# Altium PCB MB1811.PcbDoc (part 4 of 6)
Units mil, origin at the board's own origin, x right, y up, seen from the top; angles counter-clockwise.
Board outline 3480.3 x 4291.34 mil, 4 copper layers (Top Layer, L2_VCC, L3_GND, Bottom Layer), stack 30.59 mil thick; 371 components, 285 nets, 1369 pads, 606 vias.
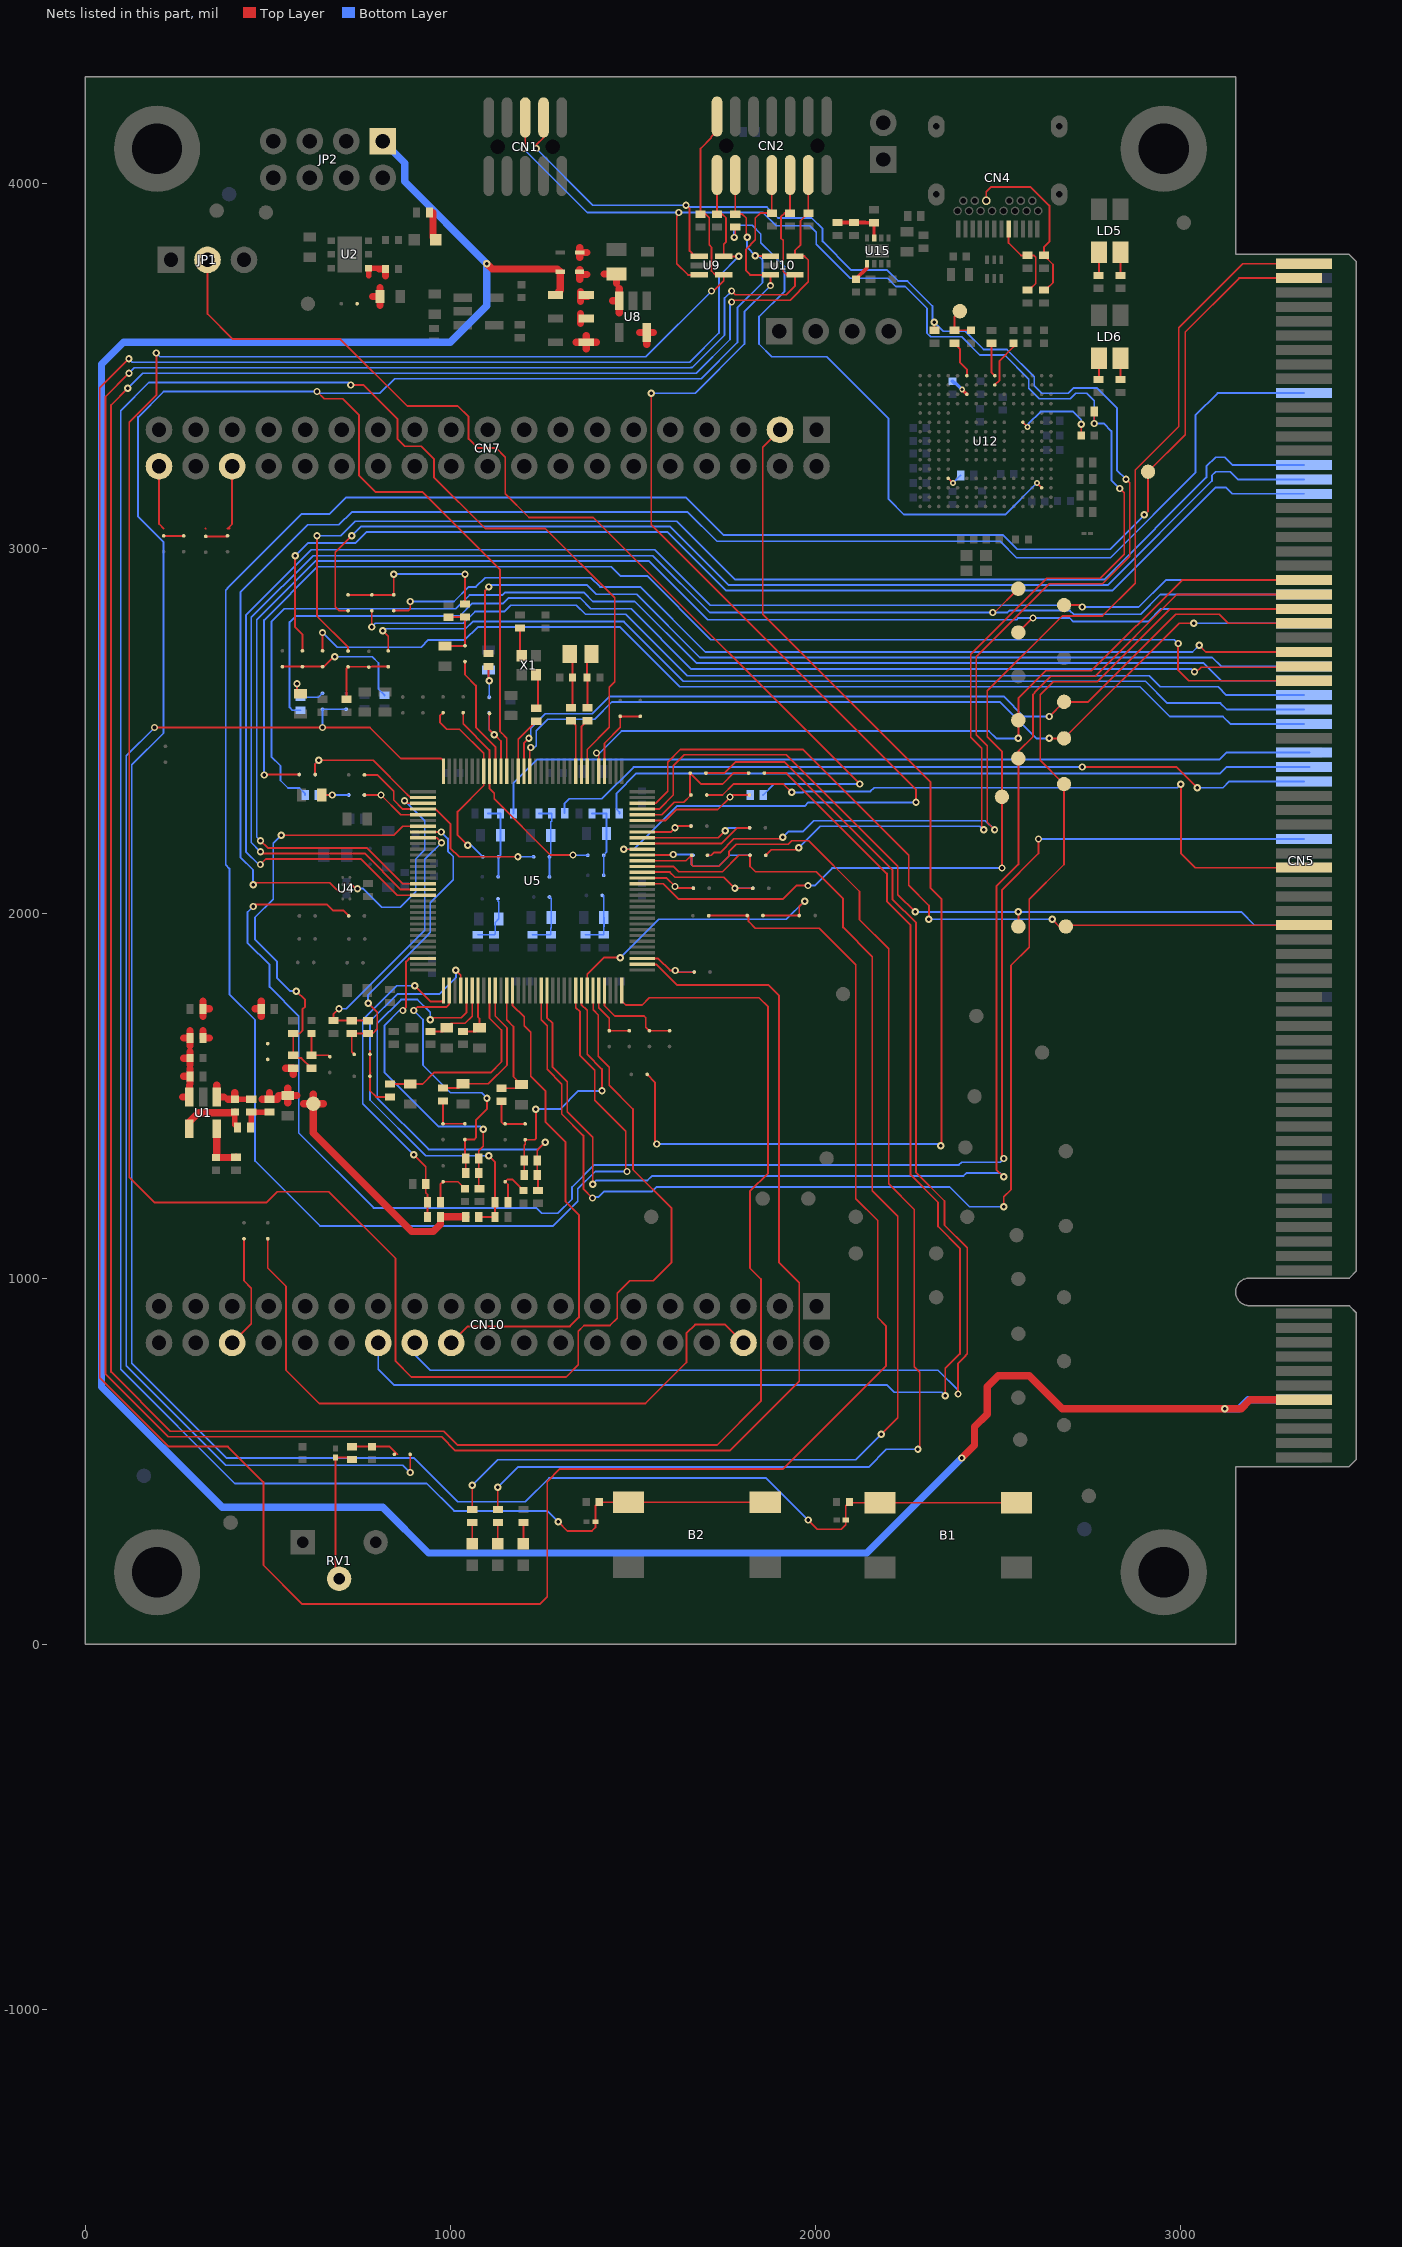
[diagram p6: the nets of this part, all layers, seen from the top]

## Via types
v1: diameter 20, hole 10, Top Layer to Bottom Layer, tented both sides, 524 vias
v2: diameter 16, hole 8, Top Layer to Bottom Layer, tented both sides, 82 vias

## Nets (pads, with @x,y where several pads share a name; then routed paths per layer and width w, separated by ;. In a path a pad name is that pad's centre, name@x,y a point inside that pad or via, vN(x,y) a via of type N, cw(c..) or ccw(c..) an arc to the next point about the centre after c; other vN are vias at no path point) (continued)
M2_PWM_WL: CN5.B40 SB48.2 | length 1871.8
  Top Layer w5: SB48.2@1702.11,2325 1744.99,2325 1775,2355.01 1912.06,2355.01 v1(1934.87,2332.2) ; v1(2999.99,2354.7) 2999.99,2165.01 3039.01,2125.99 CN5.B40@3336.8,2125.99
  Bottom Layer w5: v1(1934.87,2332.2) 1964.93,2332.2 1967.43,2334.7 2149.87,2334.7 2159.87,2344.7 2989.99,2344.7 v1(2999.99,2354.7)
M2_Res.Ex: CN5.B53 SB7.2 | length 3600
  Top Layer w5: v1(489.99,2379.7) 491.36,2381.07 SB7.2@586.37,2381.07 ; v1(2992.49,2739.7) 2992.49,2667.07 3021.76,2637.8 CN5.B53@3336.8,2637.81
  Bottom Layer w5: v1(489.99,2379.7) 489.99,2803.79 635.9,2949.7 1440.12,2949.7 1465.12,2924.7 1538.65,2924.7 1713.34,2750.01 2982.18,2750.01 v1(2992.49,2739.7)
M2_Resolver_Cos: C19.2 R20.2 R96.2 SB33.2 | length 179.4
  Top Layer w5: C19.2@984.99,2732.56 1038.91,2732.56 SB33.2@1039.99,2733.64 R20.2@1039.99,2812.3 995.19,2812.3 R96.2@994.87,2811.98
M2_Resolver_Cos_C: CN5.B55 SB27.1 | length 2639.9
  Top Layer w5: SB27.1@844.83,2830 884.87,2830 889.87,2835 v1(889.87,2854.7) ; v1(3049.87,2734.7) 3068.03,2716.54 CN5.B55@3336.8,2716.55
  Bottom Layer w5: v1(889.87,2854.7) 1009.87,2854.7 1049.87,2894.7 1069.87,2894.7 1094.87,2919.7 1384.87,2919.7 1409.87,2894.7 1519.87,2894.7 1698.03,2716.54 3031.71,2716.54 v1(3049.87,2734.7)
M2_Resolver_Sin: C24.2 R25.2 SB36.2 | length 137.8
  Top Layer w5: v1(579.87,2629.86) 579.87,2612.26 C24.2@589.87,2602.26
  Bottom Layer w5: v1(579.87,2629.86) 579.87,2602.42 R25.2@589.87,2592.42 638.97,2592.42 SB36.2@649.87,2603.32
M2_Resolver_Sin_C: CN5.B54 R25.1 | length 3161.4
  Top Layer w5: v1(3037.36,2662.19) 3042.38,2662.19 3055.2,2675.01 3334.63,2675.01 CN5.B54@3336.8,2677.18
  Bottom Layer w5: R25.1@589.87,2556.98 567.59,2556.98 559.87,2564.7 559.87,2798.47 576.1,2814.7 1024.87,2814.7 1059.87,2849.7 1144.87,2849.7 1159.87,2864.7 1354.87,2864.7 1384.87,2834.7 1494.87,2834.7 1659.87,2669.7 3029.85,2669.7 v1(3037.36,2662.19)
M2_SHUNT1+: SB17.1 SB78.2 U5.36 | length 608.6
  Top Layer w5: SB17.1@764.68,2380.01 799.55,2380.01 844.87,2334.69 844.87,2311.35 869.68,2286.54 U5.36@924.99,2286.55 959.33,2286.54 999.87,2246 999.87,2179.69 1023.81,2155.75 v1(1184.87,2155.75)
  Bottom Layer w5: v1(1184.87,2155.75) SB78.2@1227.91,2155.75
M2_SHUNT1+_C: CN5.A46 R65.1 | length 2123.2
  Top Layer w5: v1(2729.87,2401.58) 2988.42,2401.58 v1(3044.99,2345.01)
  Bottom Layer w5: R65.1@1312.71,2275.01 1312.7,2302.53 1324.87,2314.7 1414.88,2314.7 1501.76,2401.58 v1(2729.87,2401.58) ; v1(3044.99,2345.01) 3115.19,2345.01 3132.39,2362.21 CN5.A46@3336.8,2362.22
M2_SHUNT2+: SB34.1 SB74.2 U5.24 | length 591.4
  Top Layer w5: SB34.1@1034.99,2550.33 1034.99,2520.01 1106.88,2448.12 1106.88,2343.12 1119.99,2330.01 1119.99,2314.57 1273.87,2160.69 v1(1335.87,2160.69)
  Bottom Layer w5: v1(1335.87,2160.69) 1336.56,2160 SB74.2@1376.37,2160
M2_SHUNT2+_C: CN5.A47 R61.1 | length 1984.9
  Bottom Layer w5: R61.1@1462.6,2274.7 1462.59,2278.44 1454.87,2286.16 1454.87,2329.69 1509.26,2384.08 3107.24,2384.08 3124.74,2401.58 CN5.A47@3336.8,2401.59 CN5.A47@3351.8,2401.58
M2_SHUNT3+: SB30.1 SB79.2 U5.25 | length 531.6
  Top Layer w5: SB30.1@980,2550.32 971.15,2541.48 971.15,2523.85 989.99,2505.01 1024.99,2505.01 1091.13,2438.87 1091.13,2350.96 1019.87,2279.7 1019.87,2215.42 v1(1047.73,2187.56)
  Bottom Layer w5: v1(1047.73,2187.56) 1057.13,2187.56 SB79.2@1088.62,2156.07
M2_SHUNT3+_C: CN5.A48 R67.1 | length 2296.5
  Bottom Layer w5: R67.1@1172.59,2274.7 1172.59,2357.42 1237.68,2422.51 3106.3,2422.51 3124.74,2440.95 3336.8,2440.95 CN5.A48@3351.8,2440.95
M2_TEMP_ID: C5.2 R73.2 SB87.2 | length 116.1
  Top Layer w5: C5.2@647.55,2325.01 v1(676.84,2325.01) v1@679.99,2325.01
  Bottom Layer w5: R73.2@637.71,2325.01 v1(676.84,2325.01) SB87.2@721.37,2325.01
M2_TEMP_ID_C: CN5.A53 R73.1 | length 3491.7
  Bottom Layer w5: R73.1@602.28,2325.01 602.28,2328.75 586.93,2344.1 555.47,2344.1 534.87,2364.7 534.87,2404.7 509.87,2429.7 509.87,2799.69 544.88,2834.7 1014.87,2834.7 1052.37,2872.2 1142.37,2872.2 1149.87,2879.7 1364.87,2879.7 1389.87,2854.7 1504.87,2854.7 1673.03,2686.54 3061.13,2686.54 3109.87,2637.8 CN5.A53@3336.8,2637.81
M2_Timer_ETR: CN5.A42 SB16.2 | length 4708.8
  Top Layer w5: v1(459.87,2019.7) 465.18,2025.01 662.34,2025.01 678.37,2008.98 706.34,2008.98 SB16.2@721.37,1993.95 ; v1(2514.87,1329.7) 2509.99,1334.58 2509.99,2064.81 2609.99,2164.81 v1(2609.99,2204.73)
  Bottom Layer w5: v1(459.87,2019.7) 444.87,2004.7 444.87,1919.7 504.87,1859.7 504.87,1799.7 584.87,1719.7 584.87,1399.69 789.86,1194.7 1234.88,1194.7 1249.88,1179.7 1294.2,1179.7 1332.87,1218.37 1332.87,1251.67 1393.4,1312.2 2392.37,1312.2 2399.87,1319.7 2504.87,1319.7 v1(2514.87,1329.7) ; v1(2609.99,2204.73) CN5.A42@3336.8,2204.74
M2_VBUS: C4.2 R72.2 SB86.2 | length 114.3
  Top Layer w5: R72.2@1104.56,2676.86 1104.56,2639.41 v1(1106.24,2637.73)
  Bottom Layer w5: C4.2@1104.56,2667.02 1104.56,2639.41 v1(1106.24,2637.73) SB86.2@1106.24,2593.21
M2_VBUS_C: CN5.A54 R72.1 | length 2516.7
  Top Layer w5: R72.1@1104.56,2712.29 1094.87,2721.98 1094.87,2884.7 v1(1104.87,2894.7)
  Bottom Layer w5: v1(1104.87,2894.7) 1109.87,2899.7 1374.87,2899.7 1399.87,2874.7 1509.87,2874.7 1683.03,2701.54 3085.51,2701.54 3109.87,2677.18 CN5.A54@3336.8,2677.18
M2_VOL+_U_C: CN5.A50 SB10.1 | length 2886
  Top Layer w5: SB10.1@649.99,2719.69 v1(649.99,2769.7)
  Bottom Layer w5: v1(649.99,2769.7) 689.99,2729.7 919.87,2729.7 939.87,2749.7 1039.87,2749.7 1074.87,2784.7 1464.87,2784.7 1628.03,2621.54 2888.02,2621.54 2969.55,2540.01 3115,2540.01 3135.32,2519.69 CN5.A50@3336.8,2519.7
M2_VOL+_V_C: CN5.A51 SB25.1 | length 2693.3
  Top Layer w5: v1(814.99,2775.01) 829.99,2760.01 SB25.1@829.99,2719.69
  Bottom Layer w5: v1(814.99,2775.01) 819.99,2780.01 1041.4,2780.01 1061.09,2799.7 1474.88,2799.7 1638.04,2636.54 2903.02,2636.54 2963,2576.56 3108.19,2576.56 3125.69,2559.06 CN5.A51@3336.8,2559.07
M2_VOL+_W_C: CN5.A52 SB24.1 | length 2723.4
  Top Layer w5: v1(784.83,2785.01) SB24.1@784.83,2829.69
  Bottom Layer w5: v1(784.83,2785.01) 794.83,2795.01 1035.18,2795.01 1067.37,2827.2 1147.37,2827.2 1164.87,2844.7 1344.87,2844.7 1369.87,2819.7 1479.87,2819.7 1648.03,2651.54 2913.03,2651.54 2943.07,2621.5 3101.67,2621.5 3124.74,2598.43 CN5.A52@3336.8,2598.44
M3_Board_ID: CN5.A73 U4.3 | length 4405.8
  Top Layer w5: v1(459.87,2079.7) 465.18,2085.01 670.22,2085.01 682.22,2073.01 695.08,2060.17 U4.3@705.15,2060.17
  Bottom Layer w5: v1(459.87,2079.7) 459.87,2119.7 424.99,2154.58 424.99,2879.83 609.86,3064.7 694.87,3064.7 729.87,3099.7 1649.87,3099.7 1729.87,3019.7 2504.87,3019.7 2549.87,2974.7 2807.16,2974.7 3039.87,3207.41 3039.87,3364.69 3100.38,3425.2 CN5.A73@3336.8,3425.21
M3_Emergency(BKIN2): CN5.B57 TP36.1 U5.18 | length 2427.3
  Top Layer w5: U5.18@1201.37,2389.7 1201.37,2466.39 v1(1214.99,2480.01) ; v1(2639.77,2539.79) TP36.1@2679.99,2580.01 2746.21,2580.01 2985.85,2819.65 3105.35,2819.65 3129.72,2795.28 CN5.B57@3336.8,2795.29
  Bottom Layer w5: v1(1214.99,2480.01) 1219.99,2485.01 1219.99,2507.2 1260.3,2547.51 1388.67,2547.51 1436.18,2595.02 1448.64,2595.02 ; 1448.65,2595.01 2514.55,2595.01 2569.77,2539.79 v1(2639.77,2539.79)
M3_Emergency(BKIN): CN5.A57 TP35.1 U5.17 | length 2431.1
  Top Layer w5: U5.17@1217.12,2389.7 1217.11,2452.13 v1(1219.99,2455.01) ; v1(2639.87,2480.01) TP35.1@2679.99,2480.01 2995.26,2795.28 v1(3034.87,2795.28)
  Bottom Layer w5: v1(1219.99,2455.01) 1229.99,2455.01 1234.99,2460.01 1234.99,2500.98 1266.52,2532.51 1394.93,2532.51 1442.43,2580.01 2504.55,2580.01 2604.55,2480.01 v1(2639.87,2480.01) ; v1(3034.87,2795.28) CN5.A57@3336.8,2795.29
M3_Enable1: CN5.B81 TP42.1 U5.88 | length 6961.3
  Top Layer w5: U5.88@1343.1,1789.7 1343.1,1743.12 1354.99,1731.23 1354.99,1610.99 1394.99,1570.99 1394.99,1489.57 1480,1404.56 1480,1370.26 ; 1479.99,1370.25 1479.99,1299.58 1483.33,1296.24 v1(1483.33,1294.2) ; v1(2899.63,3091.93) 2900.37,3091.93 2909.99,3101.55 TP42.1@2909.99,3210.01 3011.67,3311.69 3011.67,3592.69 3159.14,3740.16 CN5.B81@3322.83,3740.17
  Bottom Layer w5: v1(1483.33,1294.2) 1396.62,1294.2 1348.87,1246.45 1348.87,1213.15 1281.13,1145.41 642.94,1145.41 464.99,1323.36 464.99,1709.79 394.87,1779.91 394.87,2123.48 384.87,2133.48 384.87,2885.92 389.87,2890.92 389.87,2892.09 592.48,3094.7 669.87,3094.7 714.87,3139.7 1644.86,3139.7 1747.93,3036.63 2513.12,3036.63 2552.15,2997.6 2806.04,2997.6 2899.63,3091.19 v1(2899.63,3091.93)
M3_Enable2: CN5.B82 TP18.1 U5.112 | length 3230.1
  Top Layer w5: U5.112@1524.99,2081.83 1583.19,2081.81 1597.49,2067.51 1597.49,2067.44 1607.74,2057.19 1607.81,2057.19 1624.99,2040.01 1909.99,2040.01 1947,2077.02 v1(1979.2,2077.02) ; v1(2509.99,2125.01) TP18.1@2509.99,2320.01 2509.99,2444.57 2469.99,2484.57 2469.99,2610.01 2674.99,2815.01 2784.99,2815.01 2874.99,2905.01 2874.99,3214.82 2994.07,3333.9 2994.07,3604.09 3169.51,3779.53 CN5.B82@3336.8,3779.54
  Bottom Layer w5: v1(1979.2,2077.02) 1997.2,2077.02 2045.19,2125.01 v1(2509.99,2125.01)
M3_PWM_UH: CN5.A58 TP27.1 U5.49 | length 4179.5
  Top Layer w5: v1(479.99,2200.01) 499.99,2180.01 771.21,2180.01 869.41,2081.81 U5.49@924.99,2081.83 ; TP27.1@2554.99,2770.01 2594.68,2809.7 v1(2594.87,2809.7)
  Bottom Layer w5: v1(479.99,2200.01) 469.99,2210.01 469.99,2805.01 630.2,2965.22 1544.34,2965.22 1704.55,2805.01 2550.3,2805.01 2554.99,2809.7 v1(2594.87,2809.7) 2695.05,2809.7 2705.05,2799.7 2909.87,2799.7 2944.83,2834.66 CN5.A58@3336.8,2834.66
M3_PWM_UL: CN5.B58 TP34.1 U5.82 | length 4104.2
  Top Layer w5: U5.82@1248.61,1789.7 1248.61,1710.05 1264.99,1693.67 1264.99,1573.67 1304.99,1533.67 1304.99,1451.69 1363.99,1392.69 1363.99,1246.58 v1(1388.87,1221.7) ; v1(2514.87,1197.51) 2514.87,1224.69 2534.87,1244.69 2534.87,1858.55 2584.87,1908.55 2584.87,2039.7 2679.99,2134.82 TP34.1@2679.99,2355.01 2614.99,2420.01 2614.99,2600.01 2649.99,2635.01 2771.21,2635.01 2970.85,2834.65 CN5.B58@3336.79,2834.65
  Bottom Layer w5: v1(1388.87,1221.7) 1391.87,1224.7 1406.08,1224.7 1421.08,1239.7 1552.06,1239.7 1564.56,1252.2 2366.46,1252.2 2421.15,1197.51 v1(2514.87,1197.51)
M3_PWM_VH: CN5.A59 TP28.1 U5.50 | length 4281.8
  Top Layer w5: v1(479.99,2170.01) 484.99,2165.01 764.99,2165.01 863.94,2066.06 U5.50@924.99,2066.08 ; v1(2484.87,2824.7) 2489.68,2824.7 TP28.1@2554.99,2890.01
  Bottom Layer w5: v1(479.99,2170.01) 454.99,2195.01 454.99,2811.23 623.98,2980.22 1554.34,2980.22 1709.86,2824.7 v1(2484.87,2824.7) 2524.87,2824.7 2529.87,2829.7 2696.27,2829.7 2706.27,2819.7 2889.68,2819.7 2944,2874.02 CN5.A59@3336.8,2874.03
M3_PWM_VL: CN5.B59 TP24.1 U5.83 | length 3949.6
  Top Layer w5: U5.83@1264.36,1789.7 1264.36,1715.52 1279.99,1699.89 1279.99,1579.89 1319.99,1539.89 1319.99,1457.91 1389.87,1388.03 v1(1389.87,1259.7) ; v1(2514.87,1279.7) 2494.99,1299.58 2494.99,2074.83 2554.99,2134.83 TP24.1@2554.99,2425.01 2554.99,2444.81 2594.99,2484.81 2594.99,2600.01 2599.99,2605.01 2599.99,2606.23 2643.77,2650.01 2764.99,2650.01 2989,2874.02 CN5.B59@3336.8,2874.03
  Bottom Layer w5: v1(1389.87,1259.7) 1399.87,1269.7 1539.62,1269.7 1552.12,1282.2 2404.81,1282.2 2412.31,1289.7 2504.87,1289.7 v1(2514.87,1279.7)
M3_PWM_WH: CN5.A60 TP38.1 U5.51 | length 4313.3
  Top Layer w5: v1(479.87,2134.7) 495.18,2150.01 754.99,2150.01 854.68,2050.32 U5.51@924.99,2050.33 ; TP38.1@2679.99,2845.01 2724.57,2845.01 v1(2729.87,2839.7)
  Bottom Layer w5: v1(479.87,2134.7) 475.3,2134.7 439.99,2170.01 439.99,2817.45 619.07,2996.53 1559.25,2996.53 1711.08,2844.7 2724.87,2844.7 v1(2729.87,2839.7) 2884.68,2839.7 2958.37,2913.39 CN5.A60@3336.8,2913.4
M3_PWM_WL: CN5.B60 TP25.1 U5.5 | length 2266.8
  Top Layer w5: v1(1399.99,2440.01) 1406.09,2433.91 U5.5@1406.09,2389.7 ; v1(2554.99,2480.01) TP25.1@2554.99,2530.01 2554.99,2590.01 2629.99,2665.01 2754.99,2665.01 3003.37,2913.39 CN5.B60@3336.8,2913.4
  Bottom Layer w5: v1(1399.99,2440.01) 1408.53,2440.01 1468.53,2500.01 2474.56,2500.01 2494.56,2480.01 v1(2554.99,2480.01)
M3_SHUNT1+_C: CN5.A66 SB9.1 | length 3247.7
  Top Layer w5: v1(574.87,2979.7) 574.87,2784.7 594.99,2764.58 SB9.1@594.99,2719.69
  Bottom Layer w5: v1(574.87,2979.7) 609.87,3014.7 739.87,3014.7 769.87,3044.7 1595.3,3044.7 1755.3,2884.7 2812.46,2884.7 3094.87,3167.11 3122.9,3167.11 3140.4,3149.61 CN5.A66@3336.8,3149.62
M3_SHUNT2+_C: CN5.A67 SB20.1 | length 3082
  Top Layer w5: SB20.1@719.83,2829.69 695.31,2829.69 684.99,2840.01 684.99,2989.82 v1(729.87,3034.7)
  Bottom Layer w5: v1(729.87,3034.7) 754.87,3059.7 1601.52,3059.7 1761.52,2899.7 2799.87,2899.7 3084.87,3184.7 3084.87,3199.69 3095.19,3210.01 3134.99,3210.01 3156.02,3188.98 CN5.A67@3336.8,3188.99
M3_SHUNT3+_C: CN5.A68 SB19.1 | length 3300.5
  Top Layer w5: v1(634.87,3034.7) 634.87,2814.69 719.83,2729.73 SB19.1@719.83,2719.37
  Bottom Layer w5: v1(634.87,3034.7) 699.87,3034.7 739.87,3074.7 1619.87,3074.7 1779.87,2914.7 2789.87,2914.7 3069.87,3194.7 3069.87,3224.71 3094.86,3249.7 3120.29,3249.7 3141.64,3228.35 CN5.A68@3336.8,3228.35
MCU.MCO: C33.2 R90.2 TP43.1 | length 103.5
  Top Layer w5: TP43.1@2394.87,3649.7 2379.87,3634.7 R90.2@2379.87,3597.42 C33.2@2424.87,3597.42
MCU.SWCLK: CN2.6 R44.2 U5.98 U10.4 | length 8662.5
  Top Layer w5: v1(119.99,3480.01) 55.99,3416.01 55.99,739.23 227.21,568.01 975.77,568.01 1013.77,530.01 1764.99,530.01 1954.99,720.01 1954.99,990.01 1899.99,1045.01 1899.99,1775.01 1869.99,1805.01 1619.99,1805.01 1563.66,1861.34 U5.98@1524.99,1861.34 ; v1(1769.87,3704.7) 1779.87,3694.7 1919.87,3694.7 1943.33,3718.16 U10.4@1943.33,3749.11 1920.45,3749.11 1911.31,3758.25 1911.31,3843.26 1904.87,3849.7 1904.87,3908.12 1914.87,3918.12 R44.2@1929.92,3918.12 1929.92,4022.3 CN2.6@1929.99,4022.37
  Bottom Layer w5: v1(119.99,3480.01) 134.68,3494.7 1658.17,3494.7 1658.48,3495.01 1661.41,3495.01 1750.48,3584.08 1750.48,3685.31 v1(1769.87,3704.7)
MCU.SWDIO: CN2.4 R45.2 U5.96 U10.5 | length 8569.2
  Top Layer w5: v1(116.58,3438.42) 70.99,3392.83 70.99,745.45 233.43,583.01 981.99,583.01 1019.99,545.01 1729.99,545.01 1849.99,665.01 1849.99,1000.01 1819.99,1030.01 1819.99,1240.01 1869.99,1290.01 1869.99,1745.01 1844.99,1770.01 1544.99,1770.01 1524.99,1750.01 1479.99,1750.01 1469.08,1760.92 U5.96@1469.08,1789.7 ; v1(1769.87,3674.7) 1774.87,3679.7 1929.87,3679.7 1979.87,3729.7 1979.87,3789.7 1969.28,3800.29 U10.5@1943.33,3800.29 1943.33,3815.67 1958.33,3830.67 1958.33,3896.53 R45.2@1979.92,3918.12 1979.92,4022.3 CN2.4@1979.99,4022.37
  Bottom Layer w5: v1(116.58,3438.42) 157.86,3479.7 1673.07,3479.7 1765.48,3572.11 1765.48,3670.31 v1(1769.87,3674.7)
MCU.SWO: CN2.8 R43.2 U5.118 U10.3 | length 3235
  Top Layer w5: v1(1474.87,2176.31) U5.118@1524.99,2176.31 ; v1(1549.87,3424.7) 1549.87,3064.7 2274.87,2339.7 v1(2274.87,2304.85) ; v1(1876.4,3719.7) U10.3@1876.4,3749.11 1820.46,3749.11 1809.48,3760.09 1809.48,3819.31 1834.87,3844.7 1834.87,3904.7 1848.29,3918.12 R43.2@1879.92,3918.12 1879.92,4022.3 CN2.8@1879.99,4022.37
  Bottom Layer w5: v1(1474.87,2176.31) 1501.48,2176.31 1619.87,2294.7 1969.87,2294.7 1979.87,2304.7 2274.72,2304.7 v1(2274.87,2304.85) ; v1(1549.87,3424.7) 1669.87,3424.7 1804.87,3559.7 1804.87,3648.17 v1(1876.4,3719.7)
MCU.VCP2_RX: CN1.3 R85.2 SB49.2 U9.1 | length 4516.5
  Top Layer w5: v1(1234.99,4095.01) 1234.99,4105.01 1254.99,4125.01 CN1.3@1254.99,4180.12 ; v1(1644.87,3939.7) 1654.87,3929.7 1654.87,3814.7 1669.28,3800.29 U9.1@1681.4,3800.29 ; SB49.2@1703.61,2160.01 1713.61,2160.01 1721.11,2167.51 1738.71,2167.51 1776.21,2205.01 1905.18,2205.01 v1(1909.87,2209.7) ; R85.2@2324.87,3597.42 v1(2324.87,3619.7) ; v1(2489.87,2229.7) 2469.87,2249.7 2469.87,2459.7 2439.87,2489.7 2439.87,2704 2639.47,2903.6 2785.37,2903.6 2859.87,2978.1 2859.87,3179.7 v1(2849.87,3189.7)
  Bottom Layer w5: v1(1234.99,4095.01) 1390.3,3939.7 v1(1644.87,3939.7) 1649.87,3934.7 1866.87,3934.7 1896.87,3904.7 1988.87,3904.7 2018.87,3874.7 2018.87,3840.7 2097.37,3762.2 2195.55,3762.2 2225.55,3732.2 2251.03,3732.2 2319.87,3663.36 2319.87,3624.7 v1(2324.87,3619.7) 2349.87,3594.7 2409.87,3594.7 2459.87,3544.7 2523.64,3544.7 2598.27,3470.07 2598.27,3445.08 2618.65,3424.7 2691.09,3424.7 2706.09,3439.7 2769.87,3439.7 2824.87,3384.7 2824.87,3214.7 v1(2849.87,3189.7) ; v1(1909.87,2209.7) 1924.87,2224.7 1964.87,2224.7 1994.87,2254.7 2464.87,2254.7 v1(2489.87,2229.7)
MCU.VCP2_TX: CN1.5 R64.2 SB58.2 U9.3 | length 4402.1
  Top Layer w5: v1(1199.99,4095.01) 1204.99,4100.01 CN1.5@1204.99,4180.12 ; v1(1624.87,3919.7) 1624.87,3914.7 1619.87,3909.7 1619.87,3779.7 1650.46,3749.11 U9.3@1681.4,3749.11 ; SB58.2@1863.62,2160.01 1878.62,2175.01 1947.68,2175.01 v1(1953.62,2180.95) ; v1(2459.87,2229.7) 2459.87,2234.7 2454.87,2239.7 2454.87,2453.48 2424.87,2483.48 2424.87,2710.22 2633.25,2918.6 2779.15,2918.6 2844.87,2984.32 2844.87,3152 v1(2832.87,3164) ; v1(2762.59,3342.3) R64.2@2762.6,3374.7
  Bottom Layer w5: v1(1199.99,4095.01) 1375.3,3919.7 v1(1624.87,3919.7) 1855.87,3919.7 1891.87,3883.7 1983.87,3883.7 2001.87,3865.7 2001.87,3832.71 2094.88,3739.7 2196.83,3739.7 2219.33,3717.2 2244.81,3717.2 2304.87,3657.14 2304.87,3589.71 2314.88,3579.7 2399.87,3579.7 2449.87,3529.7 2517.42,3529.7 2583.27,3463.85 2583.27,3438.86 2612.44,3409.69 2624.86,3409.69 2697.31,3409.7 2712.31,3424.7 2742.59,3424.7 2762.59,3404.7 v1(2762.59,3342.3) 2788.89,3342.3 2809.87,3321.32 2809.87,3187 v1(2832.87,3164) ; v1(1953.62,2180.95) 2012.37,2239.7 2449.87,2239.7 v1(2459.87,2229.7)
MCU.VCP_RX: CN2.13 R40.2 U5.91 U9.4 | length 7403.6
  Top Layer w5: v1(194.99,3535.01) 194.99,3419.81 120.99,3345.81 120.99,1279.01 190.99,1209.01 496.18,1209.01 525.87,1238.7 667.3,1238.7 849.99,1056.01 849.99,775.01 893.3,731.7 1316.68,731.7 1349.99,765.01 1349.99,856.82 1365.87,872.7 1436.87,872.7 1456.87,892.7 1456.87,961.01 1490.87,995.01 1554.99,995.01 1604.99,1045.01 1604.99,1194.57 1499.99,1299.57 1499.99,1465.01 1434.87,1530.13 1434.87,1579.71 1404.87,1609.71 1404.87,1722.7 1391.09,1736.48 1391.09,1788.95 U5.91@1390.34,1789.7 ; v1(1714.88,3704.7) 1719.88,3704.7 1748.33,3733.15 U9.4@1748.33,3749.11 1725.46,3749.11 1714.87,3759.7 1714.87,3824.69 1708.64,3830.92 1708.64,3905.92 1699.16,3915.4 R40.2@1684.92,3915.4 1684.92,4094.94 1714.37,4124.39 1714.37,4126.63 1729.99,4142.25 CN2.13@1729.99,4182.6
  Bottom Layer w5: v1(194.99,3535.01) 204.99,3525.01 1535.19,3525.01 v1(1714.88,3704.7)
MCU.VCP_TX: CN2.14 R41.2 SB51.2 SB54.2 U9.5 | length 9591.1
  Top Layer w5: v1(119.87,3519.7) 39.87,3439.7 39.87,729.69 228.56,541 391,541 488,444 488,217 594.99,110.01 1244.99,110.01 1264.99,130.01 1264.99,445.01 1299.99,480.01 1911.21,480.01 2192.49,761.29 2192.49,872.08 2169.99,894.58 2169.99,1160.01 2109.99,1220.01 2109.99,1860.01 2009.99,1960.01 1834.99,1960.01 1816.36,1978.64 1816.36,1995.01 SB54.2@1812.43,1995.01 1707.55,1995.01 SB51.2@1707.23,1994.69 ; CN2.14@1729.99,4022.37 1729.99,3932.99 1729.92,3932.92 R41.2@1729.92,3915.38 1744.2,3915.38 1754.87,3904.71 1754.87,3839.71 1748.33,3833.17 U9.5@1748.33,3800.29 1748.92,3799.7 v1(1789.87,3799.7)
  Bottom Layer w5: v1(119.87,3519.7) 129.56,3510.01 1655.19,3510.01 1735.48,3590.3 1735.48,3745.31 v1(1789.87,3799.7)
NetB2_3: B2.3 B2.4 C30.2 U5.7 U7.1 | length 6837.8
  Top Layer w5: v1(727.59,3447.41) 762.59,3447.41 854.99,3355.01 854.99,3300.01 874.99,3280.01 919.99,3280.01 954.99,3245.01 954.99,3195.01 1095.3,3054.7 1259.86,3054.7 1449.99,2864.57 1449.99,2635.01 1434.99,2620.01 1434.99,2510.01 1374.59,2449.61 U5.7@1374.6,2389.7 ; v1(1294.99,335) 1319.98,310.01 1387.28,310.01 1397.29,320.02 1397.29,379.59 C30.2@1407.71,390 1409.11,388.59 B2.3@1862,388.59
  Bottom Layer w5: v1(727.59,3447.41) 720.3,3454.7 174.87,3454.7 97.49,3377.32 97.49,752.51 409.99,440.01 934.99,440.01 1009.99,365.01 1264.98,365.01 v1(1294.99,335)
NetC1_1: C1.1 R77.2 U1.4 | length 199
  Top Layer w15: C1.1@409.87,1456.99 409.87,1421.98 R77.2@417.16,1414.7
  Top Layer w20: U1.4@285.47,1411.68 285.47,1429.7 310.47,1454.7 407.58,1454.7 C1.1@409.87,1456.99
NetC1_2: C1.2 R1.1 U1.1 | length 150.8
  Top Layer w15: C1.2@409.87,1492.42 R1.1@454.87,1492.42
  Top Layer w20: 360.27,1530.9 U1.1@360.28,1498.29 ; 379.1,1498.29 U1.1@360.28,1498.29 ; 379.47,1498.31 U1.1@360.28,1498.29 ; 391.82,1492.42 C1.2@409.87,1492.42 409.87,1509.48
NetC2_2: C2.2 R2.2 U1.5 | length 135.1
  Top Layer w20: U1.5@360.28,1411.68 360.27,1335.1 C2.2@357.87,1332.7 412.55,1332.7 R2.2@412.87,1333.02
NetC7_2: C7.2 R6.1 SB11.2 | length 111.3
  Top Layer w5: C7.2@619.87,1671.99 R6.1@619.87,1612.42 666.21,1612.42 SB11.2@669.99,1608.64
NetC11_2: C11.2 R9.2 SB26.1 | length 133.4
  Top Layer w5: R9.2@730.27,541.04 833.96,541.04 854.99,520.01
NetC12_2: C12.2 C14.2 SB12.1 U2.4 | length 154.9
  Top Layer w15: 776.99,3747.01 776.17,3747.83 U2.4@776.18,3767.61 802.62,3767.61 805.22,3765.01
  Top Layer w20: 787.81,3690.01 C12.2@807.43,3690.01 ; 805.22,3765.01 C14.2@822.28,3765.01 822.28,3746.96 ; 807.43,3665.47 C12.2@807.43,3690.01 ; 807.43,3714.55 C12.2@807.43,3690.01
NetC22_2: C22.2 R18.1 SB32.2 | length 127.1
  Top Layer w5: R18.1@972.71,1210.01 972.7,1259.09 SB32.2@979.99,1266.38 1020.91,1266.38 C22.2@1039.87,1247.42
NetC26_2: C26.2 R27.1 SB38.2 | length 124.6
  Top Layer w5: R27.1@1157.71,1210.01 1157.71,1258.67 SB38.2@1149.99,1266.39 1156.33,1272.73 1169.56,1272.73 C26.2@1199.87,1242.42
NetC29_2: C29.2 R38.1 X2.1 | length 151.9
  Top Layer w5: X2.1@1327.2,2711.29 1334.44,2704.04 C29.2@1334.44,2646.29 1334.44,2567.79 R38.1@1330.66,2564.01
NetC31_2: C31.2 R39.1 X2.2 | length 153
  Top Layer w5: R39.1@1375.66,2564.01 1375.66,2644.63 C31.2@1374,2646.29 1374,2699.04 X2.2@1386.25,2711.29
NetC32_2: C32.2 D1.2 D2.2 D3.2 D4.2 D5.2 U8.3 U8.5 | length 487.4
  Top Layer w20: 1344.11,3564.7 D5.2@1372,3564.7 ; 1353.77,3737.15 1353.77,3750.08 ; D2.2@1353.77,3763.01 1353.77,3750.08 ; 1353.76,3797.15 D1.2@1353.76,3810.08 ; 1353.76,3823.01 D1.2@1353.76,3810.08 ; 1356.45,3616.77 D4.2@1356.45,3629.7 ; 1356.45,3642.63 D4.2@1356.45,3629.7 ; 1356.45,3676.77 D3.2@1356.45,3689.7 ; D3.2@1356.45,3702.63 D3.2@1356.45,3689.7 ; 1372,3547.05 D5.2@1372,3564.7 ; 1372,3582.35 D5.2@1372,3564.7 ; 1373.59,3750.08 1353.77,3750.08 ; 1373.58,3810.08 D1.2@1353.76,3810.08 ; D4.2@1376.27,3629.7 D4.2@1372,3629.7 D4.2@1356.45,3629.7 ; D3.2@1376.27,3689.7 D3.2@1356.45,3689.7 ; 1399.89,3564.7 D5.2@1372,3564.7 ; 1420.29,3751.23 C32.2@1454.87,3751.23 1454.87,3726.49 ; 1443.64,3678.01 U8.3@1462.47,3678.01 ; 1462.47,3645.4 U8.3@1462.47,3678.01 ; 1462.47,3710.62 U8.3@1462.47,3678.01 ; 1518.44,3591.39 U8.5@1537.28,3591.39 ; 1537.27,3558.78 U8.5@1537.28,3591.39 ; 1556.1,3591.39 U8.5@1537.28,3591.39
NetC38_2: C38.2 U12.J14 | length 134.7
  Top Layer w5: U12.J14@2490.77,3447.66 2503.55,3460.45 2503.55,3513.76 2541.35,3551.56 C38.2@2541.35,3561.41
NetC43_2: C43.2 U12.M10 | length 238.5
  Top Layer w5: U12.M10@2567.54,3345.3 v2(2580.32,3332.51) ; C43.2@2727.15,3309.7 v1(2727.15,3339.7)
  Bottom Layer w5: v2(2580.32,3332.51) 2582.58,3334.77 2582.58,3341.39 2615.89,3374.7 2705.3,3374.7 2727.15,3352.85 v1(2727.15,3339.7)
NetC62_2: C62.2 U12.F13 | length 53.8
  Top Layer w10: v2(2401.19,3434.86) U12.F13@2413.99,3422.07
  Bottom Layer w10: C62.2@2374.87,3457.42 2379.87,3452.42 2383.63,3452.42 v2(2401.19,3434.86)
NetC67_2: C67.2 R61.2 R98.2 SB73.1 SB74.1 | length 205.3
  Bottom Layer w5: R98.2@1387.59,2274.7 R61.2@1427.16,2274.7 1427.55,2274.31 1427.55,2169.37 1423.87,2165.69 ; SB73.1@1419.67,2105 SB74.1@1419.67,2160
NetC68_2: C68.2 R62.2 R92.2 SB75.1 | length 157.9
  Bottom Layer w5: R92.2@1369.87,1942.42 R62.2@1419.87,1942.42 1419.87,1964.74 1420.11,1964.98 C68.2@1420.11,1990 1419.67,1990.44 SB75.1@1419.67,2050
NetC71_2: C71.2 R66.2 R91.2 SB76.1 | length 155.8
  Bottom Layer w5: R91.2@1224.87,1942.42 R66.2@1274.87,1942.42 1274.87,1959.96 1276.01,1961.1 1276.01,2040.95 SB76.1@1271.21,2045.75
NetC72_2: C72.2 R65.2 R97.2 SB77.1 SB78.1 | length 211.6
  Bottom Layer w5: R97.2@1242.59,2274.7 1276.96,2274.7 R65.2@1277.27,2275.01 1277.27,2253.73 1274.8,2251.26 1274.8,2159.34 SB78.1@1271.21,2155.75 SB77.1@1271.21,2100.75
NetC74_2: C74.2 R67.2 R99.2 SB79.1 SB80.1 | length 211.3
  Bottom Layer w5: R99.2@1102.59,2274.7 R67.2@1137.16,2274.7 1137.55,2274.3 1137.55,2161.7 SB79.1@1131.92,2156.07 1131.92,2102.44 SB80.1@1130.54,2101.06
NetC75_2: C75.2 R68.2 R93.2 SB81.1 | length 143.9
  Bottom Layer w5: R93.2@1074.87,1942.42 R68.2@1119.87,1942.42 1122.7,1945.25 1122.7,1975.9 1132.55,1985.75 1132.55,2032.45 1129.99,2035.01
NetC86_2: C86.2 R3.1 R4.2 U1.3 | length 221.9
  Top Layer w20: 266.64,1498.29 U1.3@285.47,1498.29 285.47,1530.9 ; 270.09,1554.7 R4.2@287.15,1554.7 ; 270.09,1604.7 C86.2@287.16,1604.7 ; 270.09,1659.7 R3.1@287.15,1659.7 ; 287.15,1533.9 R4.2@287.15,1554.7 ; 287.15,1575.5 R4.2@287.15,1554.7 ; 287.15,1586.65 C86.2@287.16,1604.7 ; 287.15,1622.75 C86.2@287.16,1604.7 ; 287.15,1638.9 R3.1@287.15,1659.7 ; 287.15,1680.5 R3.1@287.15,1659.7
NetC87_2: C87.2 U15.1 | length 54.5
  Top Layer w10: C87.2@2109.87,3737.42 2140.35,3767.9 U15.1@2140.35,3779.27
NetCN4_A5: CN4.A5 R35.1 R54.2 | length 230.6
  Top Layer w5: CN4.A5@2528.26,3874.79 2528.26,3836.31 2562.16,3802.41 2597.16,3802.41 2602.37,3797.2 2602.37,3725.37 2589.2,3712.2 2588.39,3712.2 2583.61,3707.42 R54.2@2579.87,3707.42
NetCN4_B5: CN4.B5 R55.2 R56.1 | length 484.8
  Top Layer w5: CN4.B5@2467.23,3951.96 2467.23,3977.16 2479.57,3989.5 2588.97,3989.5 2639.87,3938.6 2639.87,3839.7 2624.87,3824.7 R56.1@2624.87,3802.41 2649.87,3777.41 2649.87,3727.88 2634.19,3712.2 2629.66,3712.2 R55.2@2624.87,3707.41
NetCN7_3: CN7.3 SB42.2 | length 3164.8
  Top Layer w5: SB42.2@1538.61,1560.01 1559.87,1538.75 1559.87,1374.7 v1(1564.87,1369.7) ; CN7.3@1902.37,3325 1854.99,3277.62 1854.99,2820.01 2314.87,2360.13 2314.87,2069.7 2344.99,2039.58 2344.99,1367.2 v1(2342.49,1364.7)
  Bottom Layer w5: v1(1564.87,1369.7) 2337.49,1369.7 v1(2342.49,1364.7)
NetCN7_34: CN7.34 SB62.1 SB63.1 | length 236.3
  Top Layer w5: SB62.1@330,3033 388.41,3033 SB63.1@389.87,3034.46 ; 389.87,3054.39 402.37,3066.89 CN7.34@402.37,3225
NetCN7_38: CN7.38 SB64.1 SB65.1 | length 230.8
  Top Layer w5: CN7.38@202.37,3225 202.37,3066.89 214.88,3054.38 ; SB65.1@214.87,3034.46 SB64.1@269.87,3034.45
NetCN10_6: CN10.6 SB3.1 | length 1828.1
  Top Layer w5: SB3.1@499.99,1110.32 499.99,1030.01 549.99,980.01 549.99,750.01 640.99,659.01 1533.98,659.01 1646.29,771.32 1646.29,851.32 1669.98,875.01 1752.36,875.01 CN10.6@1802.37,825
NetCN10_24: CN10.24 SB50.1 | length 3745.6
  Top Layer w5: SB50.1@1699.68,2385.01 1749.99,2385.01 1779.99,2415.01 1914.99,2415.01 2209.99,2120.01 2209.99,2040.01 2274.99,1975.01 2274.99,1291.34 2352.8,1213.53 2352.8,1147.2 2414.99,1085.01 2414.99,795.01 2409.99,790.01 2409.99,788.79 2389.99,768.79 v1(2389.99,685.01)
  Bottom Layer w5: CN10.24@902.37,825 902.37,792.63 944.99,750.01 2334.99,750.01 2389.99,695.01 v1(2389.99,685.01)
NetCN10_26: CN10.26 SB57.1 | length 3633.7
  Top Layer w5: SB57.1@1859.68,2385.01 1919.99,2385.01 2194.99,2110.01 2194.99,2033.79 2259.99,1968.79 2259.99,1285 2334.99,1210 2334.99,1143.79 2394.99,1083.79 2394.99,795.01 2354.99,755.01 v1(2354.99,680.01)
  Bottom Layer w5: CN10.26@802.37,825 802.37,752.63 844.99,710.01 2194.99,710.01 2214.99,690.01 2344.99,690.01 v1(2354.99,680.01)
NetCN10_34: CN10.34 SB2.1 | length 315.4
  Top Layer w5: CN10.34@402.37,825 454.99,877.62 454.99,975.01 434.99,995.01 SB2.1@434.99,1110.32
NetJP1_2: JP1.2 R60.2 | length 2836.8
  Top Layer w5: JP1.2@334.99,3790 334.99,3642.29 404.27,3573.01 698.89,3573.01 881.89,3390.01 1019.99,3390.01 1049.99,3360.01 1049.99,3300.01 1074.99,3275.01 1124.99,3275.01 1149.99,3250.01 1149.99,3150.01 1215.3,3084.7 1391.08,3084.7 v1(2120.48,2355.3)
  Bottom Layer w5: R60.2@1856.21,2325.01 1886.49,2355.3 v1(2120.48,2355.3)
NetLD1_2: LD1.2 R32.1 | length 57.8
  Top Layer w5: LD1.2@1199.83,275.67 R32.1@1199.83,333.43
NetLD2_2: LD2.2 R28.1 | length 57.8
  Top Layer w5: LD2.2@1129.83,275.67 R28.1@1129.83,333.43
NetLD3_2: LD3.2 R23.1 | length 57.8
  Top Layer w5: LD3.2@1059.83,275.67 R23.1@1059.83,333.43
NetLD4_1: LD4.1 R15.2 | length 77.9
  Top Layer w20: R15.2@952.55,3920.01 952.55,3851.98 LD4.1@959.52,3845.01
NetLD5_1: LD5.1 R88.1 | length 63.4
  Top Layer w5: LD5.1@2834.41,3810.65 2834.4,3747.89 R88.1@2834.87,3747.42
NetLD5_2: LD5.2 R89.1 | length 63.4
  Top Layer w5: R89.1@2774.87,3747.42 2775.35,3747.9 LD5.2@2775.35,3810.65
NetLD6_1: LD6.1 R47.1 | length 58.4
  Top Layer w5: LD6.1@2834.41,3520.64 2834.87,3520.17 R47.1@2834.87,3462.42
NetLD6_2: LD6.2 R46.2 | length 58.4
  Top Layer w5: R46.2@2774.87,3462.41 2775.35,3462.89 LD6.2@2775.35,3520.64
NetR1_2: R1.2 R76.1 R77.1 | length 93.2
  Top Layer w15: R77.1@452.59,1414.7 454.87,1416.98 R1.2@454.87,1456.99 R76.1@504.87,1456.98
NetR3_2: R3.2 R74.1 R75.1 SB1.1 | length 155.2
  Top Layer w20: 322.58,1680.5 R3.2@322.59,1659.7 339.64,1659.7 ; 322.59,1718.9 R74.1@322.59,1739.7 ; 322.59,1760.5 R74.1@322.59,1739.7 ; 339.65,1739.7 R74.1@322.59,1739.7 ; 465.09,1739.7 R75.1@482.16,1739.7 ; 482.15,1718.9 R75.1@482.16,1739.7 ; 482.15,1760.5 R75.1@482.16,1739.7
NetR8_1: R8.1 SB19.2 SB23.2 SB25.2 | length 200.7
  Top Layer w5: R8.1@715.66,2587.4 715.66,2671.9 SB19.2@719.83,2676.07 784.83,2676.07 785.15,2676.39 SB25.2@829.99,2676.39
NetR9_1: R9.1 RV1.2 U3.1 | length 383.3
  Top Layer w5: RV1.2@695.27,179.11 685.27,189.11 U3.1@685.27,511.02 724.85,511.02 R9.1@730.27,505.6
NetR13_1: R13.1 SB21.2 SB22.2 | length 173.7
  Top Layer w5: 779.83,1625 779.83,1565 ; 781.04,1563.79 779.83,1565 ; R13.1@834.98,1498.35 796.65,1498.35 779.83,1515.17 779.83,1565
NetR19_1: R19.1 SB31.2 SB35.2 | length 122.4
  Top Layer w5: R19.1@979.99,1487.29 979.99,1425.29 SB31.2@979.71,1425.01 SB35.2@1039.71,1425.01
NetR20_1: R20.1 SB20.2 SB24.2 SB27.2 | length 458.6
  Top Layer w5: SB20.2@719.83,2872.99 844.51,2872.99 SB27.2@844.83,2873.31 v1(844.83,2929.7) ; v1(1039.87,2929.7) 1039.99,2929.58 R20.1@1039.99,2847.73
  Bottom Layer w5: v1(844.83,2929.7) v1(1039.87,2929.7)
NetR29_1: R29.1 SB37.2 SB39.2 | length 124.2
  Top Layer w5: R29.1@1139.83,1486.82 1139.83,1429.69 1144.83,1424.69 SB39.2@1204.83,1424.69
NetR31_1: R31.1 X1.1 | length 78.4
  Top Layer w5: R31.1@1189.99,2782.29 1190.38,2781.9 1190.38,2712.49 X1.1@1195.3,2705.59
NetR36_1: R36.1 X1.3 | length 95.2
  Top Layer w5: X1.3@1234.67,2654.41 1239.59,2647.52 1239.59,2567.32 R36.1@1234.99,2562.72
NetR36_2: R36.2 U5.19 | length 158
  Top Layer w5: U5.19@1185.62,2389.7 1185.62,2477.92 R36.2@1234.99,2527.29
NetR38_2: R38.2 U5.9 | length 144
  Top Layer w5: R38.2@1330.66,2528.58 1343.1,2516.14 U5.9@1343.1,2389.7
NetR39_2: R39.2 U5.8 | length 145.9
  Top Layer w5: U5.8@1358.85,2389.7 1358.85,2511.77 R39.2@1375.66,2528.58
NetR42_1: R42.1 U12.P3 | length 1632
  Top Layer w5: v1(1776.77,3851.6) 1779.87,3854.7 1779.87,3879.91 R42.1@1779.92,3879.96 ; v2(2605.97,3179.16) 2605.72,3178.91 2605.96,3178.91 U12.P3@2618.71,3166.16
  Bottom Layer w5: v1(1776.77,3851.6) 1776.77,3869.9 1791.57,3884.7 1826.09,3884.7 1849.87,3860.92 1849.87,3837.14 1884.87,3802.14 1884.87,3800.92 1914.87,3770.92 1914.87,3704.7 1844.87,3634.7 1844.87,3559.7 1879.87,3524.7 2029.87,3524.7 2199.87,3354.7 2199.87,3134.7 2241.87,3092.7 2519.43,3092.7 2605.89,3179.16 v2(2605.97,3179.16)
NetR48_1: R48.1 U12.J15 | length 92.1
  Top Layer w5: R48.1@2481.35,3561.41 2481.35,3482.66 U12.J15@2490.77,3473.25
NetR57_1: R57.1 U12.D4 | length 48.2
  Top Layer w5: U12.D4@2362.81,3191.75 v2(2375.6,3178.96)
  Bottom Layer w5: v2(2375.6,3178.96) 2396.34,3199.7 R57.1@2397.16,3199.7
NetR63_1: R63.1 R84.1 R86.1 U15.7 | length 142.1
  Top Layer w9: U15.7@2159.87,3850.29 R86.1@2159.87,3891.98
  Top Layer w10: R63.1@2059.87,3892.41 2078.65,3892.41 2135.65,3892.42 2136.09,3891.98 R86.1@2159.87,3891.98 ; U15.7@2159.87,3850.29 U15.7@2160.04,3850.13
NetR71_1: R71.1 SB4.2 SB9.2 SB10.2 | length 377.3
  Top Layer w5: SB4.2@539.99,2676.39 653.18,2676.39 680.52,2703.73 v1(683.14,2703.73)
  Bottom Layer w5: v1(683.14,2703.73) 785.84,2703.73 803.16,2686.41 803.16,2614.55 R71.1@819.99,2597.72
NetR90_1: R90.1 U12.F15 | length 102.9
  Top Layer w5: R90.1@2379.87,3561.98 2394.87,3546.98 2394.87,3509.7 2413.99,3490.58 U12.F15@2413.99,3473.25
NRST: B1.3 B1.4 C37.2 CN2.12 R42.2 U5.21 U10.1 U11.1 | length 9049
  Top Layer w5: v1(634.87,3429.7) 654.87,3409.7 704.87,3409.7 749.99,3364.58 749.99,3199.57 794.55,3155.01 868.77,3155.01 868.86,3154.92 923.43,3154.92 1135.43,2942.92 1135.43,2499.83 1139.87,2495.39 1139.87,2495.13 1154.12,2480.88 U5.21@1154.12,2389.7 ; CN2.12@1779.99,4022.37 1779.92,4022.3 R42.2@1779.92,3915.39 1799.19,3915.39 1809.87,3904.71 1809.87,3854.7 v1(1812.37,3852.2) ; v1(1834.87,3801.7) 1836.28,3800.29 U10.1@1876.4,3800.29 ; v1(1979.99,340) 2004.98,315.01 2069.98,315.01 2082.29,327.32 2082.29,379.59 C37.2@2092.71,390 2095.53,387.17 B1.3@2549.99,387.17
  Bottom Layer w5: v1(1812.37,3852.2) 1812.37,3824.2 v1(1834.87,3801.7) 1836.28,3800.29 1844.28,3800.29 1854.87,3789.7 1854.87,3728.17 1785.72,3659.02 1785.72,3563.85 1686.57,3464.7 847.18,3464.7 807.18,3424.7 639.87,3424.7 v1(634.87,3429.7) 214.87,3429.7 144.87,3359.7 144.87,3087.32 214.87,3017.32 214.87,2494.7 127.49,2407.32 127.49,768.73 386.21,510.01 899.99,510.01 1019.99,390.01 1204.99,390.01 1269.99,455.01 1864.98,455.01 v1(1979.99,340)
OPREF: C3.2 R5.2 R17.2 R26.2 R76.2 SB1.2 TP2.1 | length 902.4
  Top Layer w20: 484.07,1492.42 R76.2@504.87,1492.42 ; 504.87,1509.48 R76.2@504.87,1492.42 ; 525.67,1492.42 R76.2@504.87,1492.42 ; 530.33,1502.25 C3.2@554.87,1502.25 ; 549.07,1576.99 R5.2@569.87,1576.99 569.87,1559.93 ; 554.87,1482.63 C3.2@554.87,1502.25 ; 554.87,1521.87 C3.2@554.87,1502.25 ; 579.41,1502.25 C3.2@554.87,1502.25 ; 598.16,1479.7 TP2.1@624.87,1479.7 ; 624.87,1506.41 TP2.1@624.87,1479.7 ; 651.58,1479.7 TP2.1@624.87,1479.7 ; R26.2@1042.15,1169.7 1032.15,1169.7 1031.84,1170.01 R17.2@972.71,1170.01 972.7,1150.01 952.7,1130.01 894.55,1130.01 624.87,1399.69 TP2.1@624.87,1479.7
P5V: CN5.A05 CN5.B05 D2.1 D3.1 JP2.1 | length 8796.9
  Top Layer w20: v1(1099.87,3779.7) 1114.57,3765 1293.43,3765 D2.1@1300.43,3758 1300.62,3757.81 1300.62,3706.75 D3.1@1287.87,3694 ; v1(2399.99,510.01) 2435,545.02 2435,595.02 2469.99,630.01 2469.99,705.01 2499.99,735.01 2584.99,735.01 2674.99,645.01 v1(3119.99,645.01) 3164.99,645.01 3189.28,669.3 CN5.B05@3336.8,669.3
  Bottom Layer w20: JP2.1@814.99,4115.01 874.87,4055.13 874.87,4004.7 v1(1099.87,3779.7) 1099.87,3664.7 999.87,3564.7 104.87,3564.7 44.87,3504.7 44.87,705.13 374.99,375.01 814.99,375.01 939.99,250.01 2139.99,250.01 v1(2399.99,510.01) ; v1(3119.99,645.01) 3159.99,645.01 3184.28,669.3 CN5.A05@3336.8,669.3
PA3: SB26.2 SB36.1 SB82.1 U5.32 | length 3701.2
  Top Layer w5: v1(189.87,2509.7) v1(649.87,2509.7) 779.87,2509.7 864.56,2425.01 974.99,2425.01 980.89,2419.11 U5.32@980.9,2389.7 ; v1(889.99,470.01) SB26.2@889.99,520
  Bottom Layer w5: v1(189.87,2509.7) 112.49,2432.32 112.49,762.51 384.99,490.01 869.99,490.01 v1(889.99,470.01) ; v1(649.87,2509.7) SB36.1@649.87,2560.01 SB82.1@714.87,2560.01
PA5: SB7.1 SB91.1 U5.34 | length 413.8
  Top Layer w5: SB7.1@629.67,2381.07 629.67,2410 v1(639.68,2420.01) 788.77,2420.01 882.45,2326.33 882.45,2326.24 886.84,2321.85 886.93,2321.85 890,2318.78 891.23,2318.78 891.98,2318.03 U5.34@924.99,2318.05
  Bottom Layer w5: SB91.1@629.67,2381.06 629.67,2410 v1(639.68,2420.01)
PA6: U4.7 U5.35 | length 561
  Top Layer w5: U4.7@724.83,2079.85 730.15,2079.85 741.31,2068.69 v1(745.75,2068.69) ; v1(874.24,2309.69) 874.33,2309.69 881.74,2302.28 U5.35@924.99,2302.3
  Bottom Layer w5: v1(745.75,2068.69) 761.31,2068.69 812.49,2017.51 862.69,2017.51 904.99,2059.81 904.99,2149.82 929.99,2174.82 929.99,2254.57 874.87,2309.69 v1(874.24,2309.69)
PA8: R33.2 R83.2 SB39.1 U5.89 | length 708.7
  Top Layer w5: R83.2@1202.16,1284.7 R33.2@1202.16,1324.7 1202.16,1366.21 1204.83,1368.88 SB39.1@1204.83,1381.38 1231.36,1381.38 1234.02,1384.04 v1(1234.02,1465.01) ; U5.89@1358.85,1789.7 1358.85,1751.15 1374.87,1735.13 1374.87,1614.69 1414.99,1574.57 v1(1414.99,1515.01)
  Bottom Layer w5: v1(1234.02,1465.01) 1300.18,1465.01 1350.18,1515.01 v1(1414.99,1515.01)
PA9: SB54.1 SB60.1 U5.90 | length 865.6
  Top Layer w5: U5.90@1374.6,1789.7 1374.59,1834.61 1419.68,1879.7 v1(1464.87,1879.7) ; SB54.1@1859.67,1995.01 SB60.1@1955.31,1995.01 1955.3,2020.32 1969.5,2034.52 v1(1970.48,2034.52)
  Bottom Layer w5: v1(1464.87,1879.7) 1569.87,1984.7 1919.68,1984.7 1969.5,2034.52 v1(1970.48,2034.52)
PA11: SB40.1 SB43.1 U5.92 | length 177
  Top Layer w5: U5.92@1406.09,1789.7 1406.09,1742.7 1434.99,1713.8 SB40.1@1434.99,1679.7 SB43.1@1489.99,1679.69
PA12: SB45.1 SB46.1 U5.93 | length 262.9
  Top Layer w5: U5.93@1421.84,1789.7 1421.84,1748.17 1450,1720.01 1529.99,1720.01 1534.99,1715.01 1534.99,1689.69 SB45.1@1544.99,1679.69 SB46.1@1599.99,1679.69
PA15: SB53.1 SB69.1 U5.99 | length 204.5
  Top Layer w5: U5.99@1524.99,1877.1 1569.13,1877.09 1601.53,1844.69 v1(1615.31,1844.69) 1620.31,1839.69 SB53.1@1663.61,1839.69
  Bottom Layer w5: v1(1615.31,1844.69) 1620.31,1839.69 SB69.1@1663.61,1839.69
PB0: R5.1 R6.2 R78.2 U5.39 | length 1185.6
  Top Layer w5: v1(536.99,2215.01) 845.19,2215.01 869.47,2239.29 U5.39@924.99,2239.31 ; v1(578.28,1788.11) 602.38,1764.01 602.38,1745.39 594.87,1737.88 594.87,1679.7 587.15,1671.98 R78.2@569.87,1671.98 R5.1@569.87,1612.42 577.59,1604.7 592.16,1604.7 R6.2@619.87,1576.99
  Bottom Layer w5: v1(536.99,2215.01) 514.87,2192.89 514.87,2039.69 464.87,1989.69 464.87,1929.7 524.87,1869.7 524.87,1824.69 561.45,1788.11 v1(578.28,1788.11)
PB1: R11.2 R79.2 SB22.1 U5.40 | length 844.3
  Top Layer w5: SB22.1@736.53,1615 729.87,1621.65 R11.2@729.87,1671.98 787.15,1671.98 799.87,1684.7 799.87,1729.7 v1(774.87,1754.7) ; U5.40@924.99,2223.54 v1(975.03,2223.54)
  Bottom Layer w5: v1(774.87,1754.7) 774.87,1777.97 939.87,1942.97 939.87,1943.67 944.87,1948.67 944.87,2029.89 1007.84,2092.86 1007.84,2156.73 993.09,2171.48 993.09,2205.48 v1(975.03,2223.54)
PB2: R7.2 R11.1 R79.1 U5.41 | length 772.4
  Top Layer w5: v1(694.99,1740.01) 679.87,1724.89 R7.2@679.87,1707.42 R79.1@774.87,1707.42 ; U5.41@924.99,2207.81 962.19,2207.8 v1(975.59,2194.4)
  Bottom Layer w5: v1(694.99,1740.01) 714.99,1740.01 929.87,1954.89 929.87,2148.68 v1(975.59,2194.4)
PB4: SB56.1 U5.119 | length 311.9
  Top Layer w5: U5.119@1524.99,2192.05 1742.03,2192.05 1784.98,2235 SB56.1@1819.11,2235
PB5: SB68.1 U5.120 | length 305.4
  Top Layer w5: U5.120@1524.99,2207.81 1732.78,2207.8 v1(1752.49,2227.51)
  Bottom Layer w5: v1(1752.49,2227.51) 1759.99,2235.01 1799.11,2235.01 SB68.1@1819.12,2235
PB6: SB47.1 SB72.1 U5.121 | length 186.5
  Top Layer w5: U5.121@1524.99,2223.54 1603.52,2223.54 v1(1614.99,2235.01) 1619.98,2240 SB47.1@1658.81,2240
  Bottom Layer w5: v1(1614.99,2235.01) 1619.98,2240 SB72.1@1658.81,2240
PB8-BOOT0: R60.1 SB55.1 U5.123 | length 380.3
  Top Layer w5: U5.123@1524.99,2255.04 1588.8,2255.04 1618.77,2285.01 1731.21,2285.01 v1(1765.6,2319.4) 1771.2,2325 SB55.1@1818.81,2325
  Bottom Layer w5: v1(1765.6,2319.4) 1771.2,2325.01 R60.1@1820.77,2325.01
PB9: SB48.1 SB50.2 SB57.2 U5.124 | length 405.7
  Top Layer w5: U5.124@1524.99,2270.8 1578.21,2270.79 1612.43,2305.01 1638.81,2305.01 SB48.1@1658.81,2325 ; SB48.1@1656.37,2322.43 1658.8,2324.86 SB48.1@1658.81,2325 ; SB57.2@1816.38,2385.01 1774.99,2385.01 1744.99,2355.01 1686.37,2355.01 SB50.2@1656.38,2385.01 1656.37,2327.43 SB48.1@1658.81,2325
PB10: R22.1 R24.2 R81.1 U5.62 | length 886.4
  Top Layer w5: v1(869.99,1735.01) 878.84,1743.86 878.84,1868.86 887.07,1877.09 U5.62@924.99,1877.1 ; R24.2@1079.87,1247.42 1079.87,1252.42 1077.59,1254.7 1077.59,1351.17 1089.99,1363.57 v1(1089.99,1410.01)
  Bottom Layer w5: v1(869.99,1735.01) 860.19,1735.01 819.99,1694.81 819.99,1565.01 967.27,1417.73 1082.27,1417.73 v1(1089.99,1410.01)
PB11: R17.1 R18.2 R80.2 U5.65 | length 917.1
  Top Layer w5: v1(899.87,1339.7) 932.59,1306.98 932.59,1235.97 937.27,1231.29 R17.1@937.27,1170.01 ; v1(902.37,1802.63) 944.99,1760.01 975.89,1760.01 980.89,1765.01 U5.65@980.9,1789.7
  Bottom Layer w5: v1(899.87,1339.7) 759.99,1479.58 759.99,1710.01 852.61,1802.63 v1(902.37,1802.63)
PB12: R22.2 R81.2 SB35.1 U5.66 | length 760.3
  Top Layer w5: v1(899.99,1735.01) 909.99,1745.01 989.99,1745.01 996.64,1751.66 U5.66@996.64,1789.7 ; R81.2@1042.16,1289.7 R22.2@1042.16,1329.7 1039.71,1332.15 SB35.1@1039.71,1381.7 1064.99,1381.7 1069.99,1386.7 1069.99,1435.01 1099.99,1465.01 v1(1099.99,1495.01)
  Bottom Layer w5: v1(899.99,1735.01) 924.99,1710.01 924.99,1585.01 1000.3,1509.7 1085.3,1509.7 v1(1099.99,1495.01)
PB14: R26.1 R27.2 R82.2 U5.68 | length 1188.1
  Top Layer w5: v1(1014.99,1845.01) 1028.14,1831.86 U5.68@1028.14,1789.7 ; R26.1@1077.59,1169.7 R82.2@1122.16,1169.7 1122.37,1169.92 1122.37,1319.82 v1(1104.99,1337.2)
  Bottom Layer w5: v1(1014.99,1845.01) 1014.99,1825.01 969.99,1780.01 854.99,1780.01 779.99,1705.01 779.99,1490.01 932.8,1337.2 v1(1104.99,1337.2)
PB15: R33.1 R37.2 R83.1 U5.69 | length 1247.6
  Top Layer w5: v1(944.99,1710.01) 949.99,1715.01 1029.99,1715.01 1043.89,1728.91 U5.69@1043.89,1789.7 ; R37.2@1239.87,1242.42 1239.87,1282.42 R83.1@1237.59,1284.7 1237.59,1352.42 v1(1259.87,1374.7)
  Bottom Layer w5: v1(944.99,1710.01) 944.99,1730.01 909.99,1765.01 865.19,1765.01 799.99,1699.81 799.99,1495.01 940.3,1354.7 1239.87,1354.7 v1(1259.87,1374.7)
PC0: SB14.1 SB86.1 U5.22 | length 239.6
  Top Layer w5: SB14.1@1106.25,2549.91 1106.25,2503.99 v1(1120.11,2490.13) 1121.09,2490.13 1138.37,2472.85 U5.22@1138.38,2389.7
  Bottom Layer w5: SB86.1@1106.24,2549.9 1106.24,2504 v1(1120.11,2490.13)
PC1: SB33.1 U5.23 | length 335.5
  Top Layer w5: SB33.1@1039.99,2690.33 1039.99,2654.58 1069.87,2624.7 1069.87,2510.13 1123.37,2456.63 1123.37,2390.43 U5.23@1122.63,2389.7
PC4: SB15.1 SB87.1 U5.37 | length 228.1
  Top Layer w5: SB15.1@764.67,2325.01 v1(809.99,2325.01) 864.21,2270.79 U5.37@924.99,2270.8
  Bottom Layer w5: SB87.1@764.67,2325.01 v1(809.99,2325.01)
PD3: SB52.1 SB70.1 U5.113 | length 204.2
  Top Layer w5: U5.113@1524.99,2097.57 1592.44,2097.56 1614.99,2075.01 v1(1614.99,2074.69) 1619.67,2070.01 SB52.1@1665.31,2070.01
  Bottom Layer w5: v1(1614.99,2074.69) 1619.67,2070.01 SB70.1@1665.31,2070.01
PD4: SB59.1 SB66.1 U5.114 | length 363
  Top Layer w5: U5.114@1524.99,2113.32 1525.74,2114.06 1600.94,2114.06 1614.99,2100.01 1748.96,2100.01 v1(1778.96,2070.01) 1779.28,2069.69 SB59.1@1824.08,2069.69
  Bottom Layer w5: v1(1778.96,2070.01) 1779.29,2069.68 SB66.1@1824.08,2069.68
PD5: R23.2 SB58.1 U5.115 | length 3432.4
  Top Layer w5: R23.2@1059.83,368.86 1059.83,434.85 v1(1059.99,435.01) ; U5.115@1524.99,2129.07 1610.94,2129.06 1624.99,2115.01 1744.99,2115.01 1789.99,2160.01 1820.31,2160.01 1820.31,2129.69 1835.3,2114.7 2001.08,2114.7 2074.99,2040.79 2074.99,1962.45 2154.99,1882.45 2154.99,1241.46 2224.99,1171.46 2224.99,620.01 v1(2179.99,575.01)
  Bottom Layer w5: v1(1059.99,435.01) 1129.99,505.01 2109.99,505.01 v1(2179.99,575.01)
PD6: R28.2 SB49.1 U5.116 | length 3573.9
  Top Layer w5: R28.2@1129.83,368.86 v1(1129.83,430.01) ; U5.116@1524.99,2144.82 1645.1,2144.8 SB49.1@1660.31,2160.01 1660.31,2135.01 1665.31,2130.01 1734.99,2130.01 1762.49,2157.51 1762.49,2170.07 1782.43,2190.01 1925.18,2190.01 1934.87,2199.7 1981.08,2199.7 2119.99,2060.79 2119.99,1983.91 2199.99,1903.91 2199.99,1260.12 2269.99,1190.12 2269.99,760 2284.99,745 2284.99,538.71 v1(2279.99,533.71)
  Bottom Layer w5: v1(1129.83,430.01) 1184.83,485.01 2144.99,485.01 2193.69,533.71 v1(2279.99,533.71)
PD7: SB67.1 SB71.1 U5.117 | length 337
  Top Layer w5: U5.117@1524.99,2160.55 1608.24,2160.55 v1(1609.99,2162.3)
  Bottom Layer w5: v1(1609.99,2162.3) 1658.02,2162.3 1660.31,2160.01 1659.99,2159.69 1659.99,2135.01 1664.99,2130.01 1734.99,2130.01 1764.99,2160.01 SB67.1@1820.31,2160.01
PD8: C20.2 R16.2 U5.70 | length 202.1
  Top Layer w5: R16.2@944.99,1677.73 980.15,1677.73 1002.43,1700.01 1039.99,1700.01 1059.63,1719.65 U5.70@1059.64,1789.7
PD9: C23.2 R21.2 U5.71 | length 153.1
  Top Layer w5: R21.2@1034.99,1677.72 1070.14,1677.72 C23.2@1079.99,1687.57 1079.99,1712.67 1075.38,1717.28 U5.71@1075.38,1789.7
PD11: C17.2 R13.2 U5.73 | length 593.8
  Top Layer w5: C17.2@890,1533.79 R13.2@834.98,1533.78 923.76,1533.78 954.99,1565.01 1109.99,1565.01 1139.99,1595.01 1139.99,1681.43 1106.88,1714.54 U5.73@1106.88,1789.7
PD12: C21.2 R19.2 U5.74 | length 418.9
  Top Layer w5: R19.2@979.99,1522.72 1023.17,1522.72 C21.2@1034.71,1534.26 1104.24,1534.26 1154.99,1585.01 1154.99,1687.65 1122.63,1720.01 U5.74@1122.63,1789.7
PD14: C25.2 R29.2 U5.76 | length 333.5
  Top Layer w5: R29.2@1139.83,1522.25 1184.99,1522.25 C25.2@1194.83,1532.09 1172.84,1554.08 1172.84,1691.02 1154.12,1709.74 U5.76@1154.12,1789.7
PD15: CN10.22 U5.77 | length 1348.8
  Top Layer w5: CN10.22@1002.37,825 1047.38,870.01 1327.18,870.01 1351.87,894.7 1351.87,1175.7 1314.87,1212.7 1314.87,1375.13 1259.99,1430.01 1259.99,1515.01 1219.99,1555.01 1219.99,1675.01 1202.11,1692.89 1202.11,1717.46 1169.87,1749.7 U5.77@1169.87,1789.7
PE0: CN5.A36 TP23.1 U5.125 | length 2198.8
  Top Layer w5: U5.125@1524.99,2286.55 1571.52,2286.54 1609.99,2325.01 1609.99,2405.01 1639.99,2435.01 1919.99,2435.01 2224.99,2130.01 2224.99,2052.51 v1(2272.49,2005.01) ; TP23.1@2554.99,1965.01 v1(2554.99,2005.01)
  Bottom Layer w5: v1(2272.49,2005.01) v1(2554.99,2005.01) 3164.98,2005.01 3201.48,1968.51 CN5.A36@3336.8,1968.51
PE1: CN5.B36 TP41.1 U5.126 | length 2192.5
  Top Layer w5: U5.126@1524.99,2302.3 1562.26,2302.28 1594.99,2335.01 1594.99,2415.01 1629.99,2450.01 1964.99,2450.01 2254.99,2160.01 2254.99,2077.57 2309.99,2022.57 v1(2309.99,1985.01) ; v1(2647.37,1984.7) 2667.06,1965.01 TP41.1@2684.99,1965.01 2688.49,1968.51 CN5.B36@3336.8,1968.51
  Bottom Layer w5: v1(2309.99,1985.01) 2310.3,1984.7 v1(2647.37,1984.7)
PE5: SB41.1 SB44.1 U5.4 | length 223.9
  Top Layer w5: U5.4@1421.84,2389.7 1421.84,2466.86 1464.99,2510.01 SB41.1@1464.99,2540.32 1470.3,2540.32 ; 1469.99,2540.01 1470.3,2540.32 ; SB44.1@1519.99,2540.32 1470.3,2540.32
